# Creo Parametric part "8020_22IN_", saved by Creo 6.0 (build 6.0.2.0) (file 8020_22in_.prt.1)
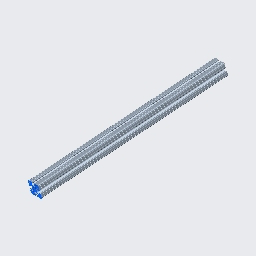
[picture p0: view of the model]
Units: Inch lbm Second (Pro/E Default); INCH, POUND, SECS

Created from: INLBS_PART_SOLID.PRT

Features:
  1. datum plane "RIGHT"
  2. datum plane "TOP"
  3. datum plane "FRONT"
  4. coordinate system
  5. curve "Project 1"
  6. sketch "Sketch 2"
  7. extrusion "Extrude 1"

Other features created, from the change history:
  sketch "Sketch 1"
